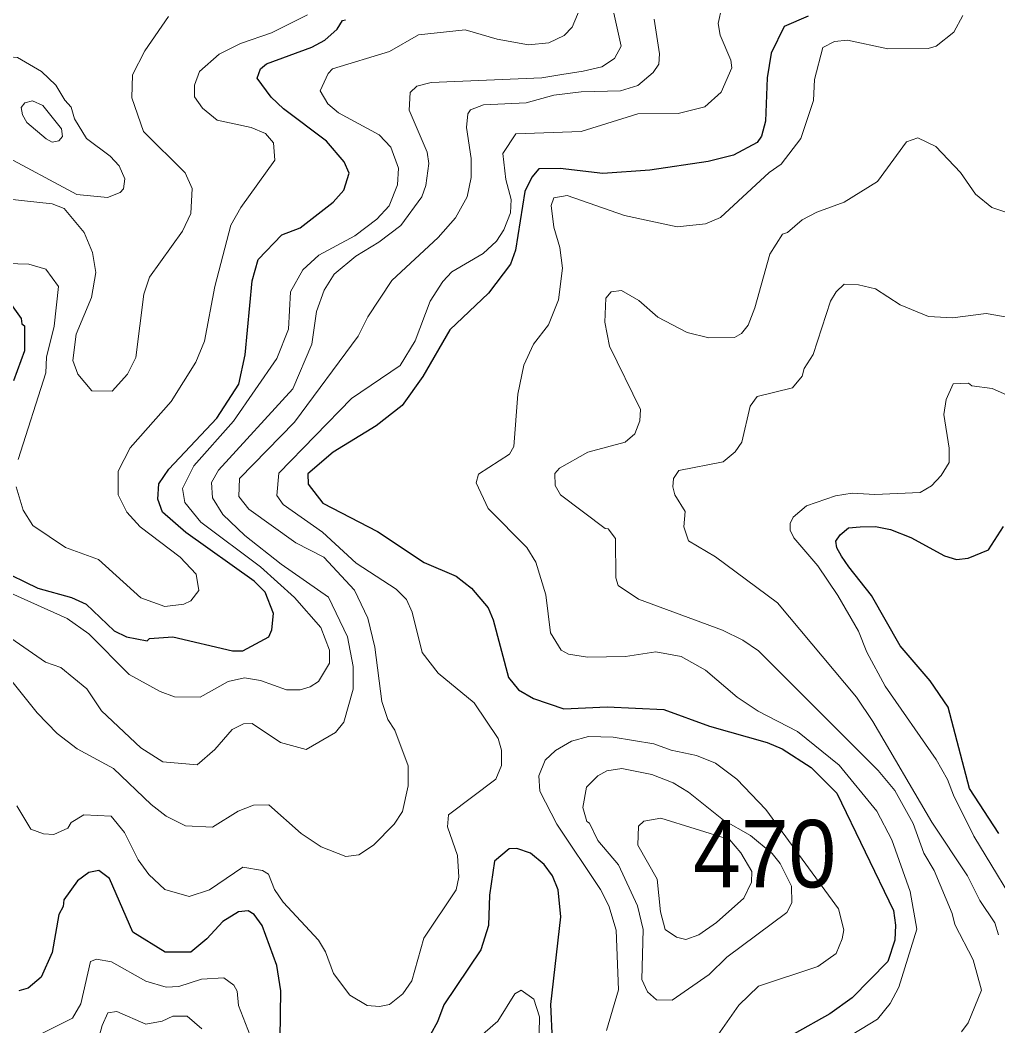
# Model space of a CAD drawing. Extents: x 673.3 to 698.5, y 6984.3 to 7012.3.
# Drawn here: x 690.061 to 691.219, y 6996.578 to 6997.77 of the extents above; entities that cross this region are included whole.
import ezdxf

# ---------------------------------------------------------------- set-up
doc = ezdxf.new("R2010")
doc.units = 0
doc.header["$LTSCALE"] = 0.032
doc.layers.add('1', color=7, linetype='Continuous', lineweight=25)
doc.layers.add('2', color=7, linetype='Continuous', lineweight=13)
doc.layers.add('21', color=7, linetype='Continuous')

msp = doc.modelspace()

# ---------------------------------------------------------------- linework, layer by layer
at = {"layer": '1'}
for points in [[(690.2418, 6997.0396), (690.3124, 6997.0228), (690.3249, 6997.0227), (690.3556, 6997.0394), (690.3593, 6997.0478), (690.361, 6997.0673), (690.3512, 6997.0925), (690.3383, 6997.1056), (690.2572, 6997.1631), (690.2298, 6997.187), (690.2243, 6997.2025), (690.2252, 6997.2209), (690.237, 6997.2381), (690.2942, 6997.2985), (690.3202, 6997.3389), (690.3276, 6997.3735), (690.3357, 6997.4612), (690.3431, 6997.4867), (690.3712, 6997.5159), (690.3927, 6997.5242), (690.4318, 6997.5544), (690.4443, 6997.5687), (690.4507, 6997.5889), (690.4449, 6997.6024), (690.4239, 6997.6266), (690.373, 6997.6649), (690.3585, 6997.6789), (690.3419, 6997.7014), (690.3457, 6997.7124), (690.3529, 6997.7183), (690.4066, 6997.7383), (690.4218, 6997.7464), (690.4364, 6997.7593), (690.4431, 6997.7699), (690.4465, 6997.7705)], [(690.9947, 6997.775), (690.9661, 6997.7627), (690.9509, 6997.7311), (690.9458, 6997.7017), (690.9441, 6997.6504), (690.9392, 6997.6326), (690.9343, 6997.6253), (690.9063, 6997.6102), (690.876, 6997.6025), (690.807, 6997.5926), (690.7513, 6997.5886), (690.7007, 6997.5943), (690.6754, 6997.5941), (690.6671, 6997.5841), (690.659, 6997.5671), (690.6477, 6997.4976), (690.6419, 6997.4811), (690.6157, 6997.4466), (690.5699, 6997.4034), (690.5379, 6997.3478), (690.5134, 6997.3135), (690.4827, 6997.2896), (690.4317, 6997.2584), (690.4019, 6997.2326), (690.4022, 6997.2205), (690.4198, 6997.198), (690.4845, 6997.1644), (690.5396, 6997.1275), (690.5776, 6997.1113), (690.5957, 6997.0972), (690.6153, 6997.074)], [(690.0483, 6997.4361), (690.0624, 6997.4166), (690.063, 6997.4105), (690.0662, 6997.4081), (690.0662, 6997.3784), (690.0533, 6997.3429)], [(691.2204, 6996.8065), (691.1855, 6996.8599), (691.1605, 6996.956), (691.1389, 6996.9873), (691.1035, 6997.0289), (691.0697, 6997.0883), (691.0428, 6997.1224), (691.0339, 6997.1351), (691.0285, 6997.1448), (691.0273, 6997.1528), (691.0325, 6997.1605), (691.0423, 6997.1685), (691.0562, 6997.1698), (691.0744, 6997.1702), (691.092, 6997.1667), (691.1162, 6997.1573), (691.1562, 6997.1355), (691.1703, 6997.131), (691.1842, 6997.1327), (691.208, 6997.1427), (691.226, 6997.1702)], [(690.0347, 6997.1201), (690.082, 6997.0973), (690.1219, 6997.0859), (690.1392, 6997.0781), (690.1723, 6997.0464), (690.1871, 6997.0393), (690.2116, 6997.0348), (690.2143, 6997.0373), (690.2418, 6997.0396)], [(690.6153, 6997.074), (690.6212, 6997.0595), (690.6394, 6996.9911), (690.6516, 6996.9765), (690.6691, 6996.9662), (690.705, 6996.9541), (690.7565, 6996.9565), (690.8236, 6996.9533), (690.8776, 6996.9336), (690.946, 6996.9141), (690.9639, 6996.9068), (690.9981, 6996.8847), (691.0286, 6996.8542), (691.0956, 6996.7152), (691.098, 6996.6979), (691.0972, 6996.6801), (691.0891, 6996.6547), (691.0465, 6996.6118), (691.0201, 6996.5927), (690.9356, 6996.5453)], [(690.6916, 6996.5612), (690.6896, 6996.604), (690.7014, 6996.7078), (690.6982, 6996.7396), (690.6916, 6996.7562), (690.682, 6996.7698), (690.6655, 6996.7831), (690.6493, 6996.7887), (690.6403, 6996.7883), (690.6231, 6996.7736), (690.617, 6996.7334), (690.6159, 6996.6976), (690.6069, 6996.6684), (690.5631, 6996.6034), (690.5555, 6996.5833), (690.5389, 6996.5533)], [(690.3692, 6996.5636), (690.3699, 6996.6201), (690.3652, 6996.65), (690.3479, 6996.6976), (690.3382, 6996.7106), (690.3313, 6996.7147), (690.3196, 6996.7135), (690.3013, 6996.7022), (690.2823, 6996.6816), (690.2633, 6996.6659), (690.2327, 6996.6658), (690.1947, 6996.6897), (690.167, 6996.753), (690.1541, 6996.7626), (690.1425, 6996.7601), (690.1289, 6996.7505), (690.1128, 6996.728), (690.1119, 6996.7201), (690.1069, 6996.7106), (690.0988, 6996.6653), (690.0859, 6996.636), (690.0707, 6996.6231), (690.0594, 6996.6202)]]:
    msp.add_lwpolyline(points, dxfattribs=at)
at = {"layer": '2'}
for points in [[(690.0303, 6997.0999), (690.1169, 6997.061), (690.1424, 6997.043), (690.19, 6996.9949), (690.2268, 6996.9747), (690.2437, 6996.9684), (690.2742, 6996.9678), (690.3075, 6996.9867), (690.3268, 6996.9907), (690.3458, 6996.9877), (690.3767, 6996.9768), (690.3926, 6996.9768), (690.4046, 6996.9802), (690.4144, 6996.9867), (690.4277, 6997.0084), (690.4276, 6997.0235), (690.4174, 6997.0506), (690.3862, 6997.086), (690.3458, 6997.1224), (690.275, 6997.1753), (690.256, 6997.1988), (690.2534, 6997.2154), (690.2668, 6997.2419), (690.3139, 6997.2948), (690.3653, 6997.3692), (690.3788, 6997.4039), (690.3813, 6997.4484), (690.3958, 6997.4743), (690.4147, 6997.4916), (690.4577, 6997.5147), (690.4836, 6997.5344), (690.4981, 6997.55), (690.5082, 6997.5749), (690.5092, 6997.5947), (690.5, 6997.6198), (690.4863, 6997.6342), (690.4383, 6997.6602), (690.4257, 6997.6711), (690.4166, 6997.6866), (690.426, 6997.7071), (690.4312, 6997.7123), (690.4984, 6997.7329), (690.533, 6997.7527), (690.5884, 6997.7588), (690.626, 6997.7478), (690.6632, 6997.7409), (690.6874, 6997.7434), (690.7057, 6997.7519), (690.7148, 6997.7618), (690.736, 6997.8121)], [(690.7628, 6997.7854), (690.773, 6997.7393), (690.7653, 6997.7249), (690.7502, 6997.7148), (690.728, 6997.7097), (690.7028, 6997.7058), (690.679, 6997.7019), (690.548, 6997.6962), (690.5311, 6997.6921), (690.5231, 6997.6844), (690.522, 6997.6636), (690.5432, 6997.6136), (690.545, 6997.6003), (690.5418, 6997.5743), (690.5368, 6997.5609), (690.512, 6997.527), (690.486, 6997.507), (690.4587, 6997.4907), (690.433, 6997.469), (690.421, 6997.4502), (690.4121, 6997.4249), (690.4064, 6997.3862), (690.3842, 6997.3335), (690.296, 6997.237), (690.2877, 6997.2225), (690.2889, 6997.204), (690.301, 6997.1844), (690.3274, 6997.1596), (690.3702, 6997.1257), (690.4264, 6997.0864), (690.449, 6997.0393), (690.4554, 6997.0045), (690.4554, 6996.9774), (690.4446, 6996.9384), (690.4346, 6996.926), (690.3999, 6996.9061), (690.3696, 6996.9144), (690.3359, 6996.9368), (690.3258, 6996.9362), (690.3121, 6996.9296), (690.2915, 6996.9058), (690.2707, 6996.8878), (690.2302, 6996.8914), (690.2041, 6996.9081), (690.1573, 6996.9519), (690.1401, 6996.978), (690.1091, 6997.0031), (690.0911, 6997.0093), (690.0399, 6997.0448)], [(690.8921, 6997.7858), (690.888, 6997.7661), (690.8902, 6997.7524), (690.9031, 6997.7228), (690.904, 6997.7137), (690.8913, 6997.6849), (690.8722, 6997.6675), (690.8405, 6997.6594), (690.7926, 6997.6593), (690.7257, 6997.6382), (690.6481, 6997.6354), (690.633, 6997.6123), (690.6364, 6997.5813), (690.6427, 6997.5576), (690.642, 6997.5417), (690.6342, 6997.5217), (690.6255, 6997.5082), (690.6095, 6997.4935), (690.5725, 6997.4718), (690.5617, 6997.4606), (690.5466, 6997.437), (690.5289, 6997.3901), (690.5113, 6997.361), (690.4536, 6997.322), (690.3676, 6997.2333), (690.3651, 6997.2069), (690.3728, 6997.1964), (690.4194, 6997.1636), (690.4591, 6997.1269), (690.5066, 6997.0958), (690.5189, 6997.0837), (690.5255, 6997.0686), (690.5374, 6997.0208), (690.5563, 6996.9966), (690.599, 6996.9612), (690.6274, 6996.9188), (690.6312, 6996.905), (690.6313, 6996.8869), (690.6246, 6996.8709), (690.5686, 6996.8284), (690.5671, 6996.8143), (690.5793, 6996.7803), (690.5809, 6996.7548), (690.5776, 6996.7395), (690.5391, 6996.6824), (690.525, 6996.6318), (690.5142, 6996.6164)], [(690.0445, 6997.5583), (690.0988, 6997.5526), (690.1132, 6997.5471), (690.137, 6997.5184), (690.1466, 6997.4947), (690.1508, 6997.4712), (690.1455, 6997.4415), (690.1273, 6997.398), (690.1233, 6997.367), (690.1292, 6997.3507), (690.1461, 6997.3308), (690.1699, 6997.3306), (690.1881, 6997.3505), (690.1981, 6997.3704), (690.2076, 6997.4456), (690.2142, 6997.4658), (690.2535, 6997.5203), (690.2631, 6997.5411), (690.2648, 6997.5706), (690.2567, 6997.5893), (690.2072, 6997.6384), (690.1933, 6997.6781), (690.194, 6997.7053), (690.2089, 6997.7338), (690.2368, 6997.7745)], [(690.4015, 6997.7765), (690.3589, 6997.7552), (690.3219, 6997.7424), (690.2967, 6997.7299), (690.2734, 6997.7093), (690.2674, 6997.693), (690.2674, 6997.6793), (690.277, 6997.666), (690.2946, 6997.6517), (690.3349, 6997.643), (690.3518, 6997.6358), (690.361, 6997.6246), (690.3627, 6997.6042), (690.3223, 6997.5483), (690.3107, 6997.5272), (690.2917, 6997.4547), (690.2795, 6997.3899), (690.2691, 6997.3648), (690.2398, 6997.3184), (690.1914, 6997.2634), (690.1771, 6997.2357), (690.1772, 6997.2078), (690.1875, 6997.187), (690.2033, 6997.1698), (690.2506, 6997.1337), (690.2696, 6997.1136), (690.2729, 6997.0943), (690.2631, 6997.082), (690.2548, 6997.0781), (690.2323, 6997.0755), (690.2042, 6997.0857), (690.1539, 6997.1309), (690.1148, 6997.1452), (690.0762, 6997.1714), (690.0646, 6997.1897), (690.0565, 6997.2172)], [(690.5043, 6996.8173), (690.5141, 6996.8323), (690.5206, 6996.863), (690.5206, 6996.8865), (690.5051, 6996.9289), (690.4966, 6996.9414), (690.4897, 6996.9628), (690.4814, 6997.0273), (690.4731, 6997.0615), (690.4572, 6997.0948), (690.4207, 6997.1339), (690.3876, 6997.1508), (690.332, 6997.1908), (690.3202, 6997.2056), (690.3208, 6997.2272), (690.3862, 6997.2937), (690.4615, 6997.3957), (690.473, 6997.4185), (690.5013, 6997.4618), (690.5562, 6997.5126), (690.5768, 6997.5359), (690.5906, 6997.5609), (690.5955, 6997.5836), (690.5955, 6997.6064), (690.5898, 6997.643), (690.5912, 6997.6591), (690.5946, 6997.664), (690.61, 6997.67), (690.6604, 6997.6723), (690.6933, 6997.6813), (690.7258, 6997.6854), (690.7721, 6997.6864), (690.7929, 6997.6929), (690.8111, 6997.708), (690.8176, 6997.7181), (690.8186, 6997.7302), (690.8121, 6997.7715)], [(690.9106, 6996.9678), (690.873, 6996.9999), (690.8441, 6997.0163), (690.8142, 6997.0218), (690.7782, 6997.0161), (690.733, 6997.0153), (690.7105, 6997.019), (690.7021, 6997.0236), (690.6892, 6997.0443), (690.6837, 6997.0891), (690.6719, 6997.1279), (690.6612, 6997.1452), (690.6155, 6997.1914), (690.6013, 6997.222), (690.604, 6997.2321), (690.6406, 6997.2558), (690.6459, 6997.265), (690.6508, 6997.3269), (690.6576, 6997.3612), (690.6692, 6997.3862), (690.6871, 6997.4093), (690.6989, 6997.4388), (690.7037, 6997.4763), (690.7005, 6997.5006), (690.6932, 6997.525), (690.69, 6997.5507), (690.6931, 6997.5596), (690.7092, 6997.5624), (690.7768, 6997.5388), (690.8394, 6997.5251), (690.873, 6997.5288), (690.8906, 6997.5365), (690.9484, 6997.5897), (690.9626, 6997.5997), (690.9858, 6997.6299), (691.001, 6997.6749), (691.0021, 6997.6999), (691.0121, 6997.7379), (691.0258, 6997.7449), (691.0413, 6997.7466), (691.089, 6997.736), (691.1369, 6997.7366), (691.1463, 6997.7393), (691.167, 6997.756), (691.1777, 6997.7755)], [(690.7, 6997.2393), (690.7334, 6997.2584), (690.7778, 6997.2702), (690.7894, 6997.2801), (690.795, 6997.2954), (690.7958, 6997.309), (690.7594, 6997.384), (690.7536, 6997.4124), (690.755, 6997.4406), (690.761, 6997.4483), (690.7733, 6997.4499), (690.794, 6997.438), (690.8165, 6997.4184), (690.8512, 6997.4002), (690.8767, 6997.3937), (690.9071, 6997.3943), (690.9157, 6997.3989), (690.9234, 6997.4088), (690.9315, 6997.4294), (690.9491, 6997.4927), (690.9642, 6997.5164), (690.9701, 6997.5185), (690.9873, 6997.5336), (691.0049, 6997.5428), (691.0372, 6997.5545), (691.0767, 6997.5788), (691.1109, 6997.6258), (691.1244, 6997.6307), (691.1458, 6997.6204), (691.1752, 6997.5896), (691.1927, 6997.5639), (691.2121, 6997.548), (691.2394, 6997.539)], [(690.0588, 6997.2494), (690.0914, 6997.3524), (690.0924, 6997.371), (690.1012, 6997.4077), (690.1066, 6997.4544), (690.0915, 6997.4751), (690.0714, 6997.481), (690.0454, 6997.4818)], [(691.2201, 6996.6864), (691.2155, 6996.7004), (691.198, 6996.7272), (691.1835, 6996.7562), (691.1411, 6996.8197), (691.0713, 6996.9392), (691.0517, 6996.9678), (690.9583, 6997.0799), (690.8846, 6997.1341), (690.8528, 6997.1531), (690.8472, 6997.1697), (690.8488, 6997.1878), (690.8365, 6997.2077), (690.8342, 6997.217), (690.8351, 6997.2271), (690.8415, 6997.2366), (690.8937, 6997.2467), (690.9081, 6997.2586), (690.9161, 6997.2701), (690.926, 6997.3126), (690.9341, 6997.3243), (690.9759, 6997.3343), (690.9876, 6997.3484), (690.9898, 6997.3575), (691.0005, 6997.3741), (691.0212, 6997.4373), (691.0278, 6997.4482), (691.0373, 6997.4574), (691.0542, 6997.4566)], [(691.0542, 6997.4566), (691.0744, 6997.4517), (691.1035, 6997.4329), (691.1373, 6997.4189), (691.1654, 6997.4175), (691.2056, 6997.4224), (691.235, 6997.4176)], [(691.0059, 6997.1235), (690.9774, 6997.1569), (690.9734, 6997.1658), (690.9734, 6997.1738), (690.9767, 6997.1813), (690.9924, 6997.1948), (691.0269, 6997.2065), (691.0467, 6997.2098), (691.0737, 6997.2082), (691.1271, 6997.2105), (691.1405, 6997.2182), (691.1522, 6997.2307), (691.1615, 6997.246), (691.1615, 6997.2631), (691.1551, 6997.3028), (691.1581, 6997.3208), (691.1663, 6997.3394), (691.1846, 6997.3402), (691.1883, 6997.3369), (691.2125, 6997.3337), (691.268, 6997.3093)], [(691.1761, 6996.5715), (691.184, 6996.5821), (691.1997, 6996.6206), (691.19, 6996.6569), (691.1683, 6996.6986), (691.1651, 6996.7117), (691.1437, 6996.7624), (691.1316, 6996.7833), (691.119, 6996.8184), (691.0971, 6996.8572), (691.0773, 6996.8811), (690.9357, 6997.0227), (690.917, 6997.0357), (690.8931, 6997.0473), (690.7936, 6997.0839), (690.7696, 6997.1002), (690.7666, 6997.1095), (690.7664, 6997.1561), (690.7578, 6997.1673), (690.7541, 6997.1678), (690.7011, 6997.2079), (690.695, 6997.2186), (690.6945, 6997.233), (690.7, 6997.2393)], [(691.2537, 6996.6998), (691.191, 6996.8032), (691.1667, 6996.8518), (691.1598, 6996.8705), (691.1463, 6996.8942), (691.0857, 6996.9811), (691.064, 6997.0211), (691.054, 6997.0461), (691.0297, 6997.0883), (691.0059, 6997.1235)], [(690.0094, 6997.0386), (690.0813, 6996.9495), (690.105, 6996.9251), (690.1286, 6996.9067), (690.1718, 6996.8834), (690.2162, 6996.8407), (690.2342, 6996.8269), (690.2571, 6996.8156), (690.289, 6996.8141), (690.3195, 6996.8327), (690.3376, 6996.8399), (690.3555, 6996.8402), (690.3938, 6996.8065), (690.4175, 6996.7906), (690.4467, 6996.7792), (690.4621, 6996.7811), (690.4797, 6996.7926), (690.5043, 6996.8173)], [(691.0363, 6996.562), (691.0765, 6996.5865), (691.0917, 6996.605), (691.1021, 6996.6243), (691.1231, 6996.6929), (691.1153, 6996.7377), (691.0938, 6996.7989), (691.076, 6996.8328), (691.0313, 6996.8872), (690.9818, 6996.9271), (690.9354, 6996.9515), (690.9106, 6996.9678)], [(690.8848, 6996.5635), (690.9123, 6996.6031), (690.9357, 6996.6256), (691.006, 6996.6488), (691.0277, 6996.6644), (691.035, 6996.6815), (691.0368, 6996.6924), (691.0306, 6996.7173), (690.9445, 6996.8349), (690.9099, 6996.871), (690.8846, 6996.8897), (690.8624, 6996.8988), (690.8323, 6996.9051), (690.8119, 6996.9126), (690.7636, 6996.9207), (690.7343, 6996.9215), (690.7142, 6996.9157), (690.6952, 6996.9046), (690.6828, 6996.8932), (690.6754, 6996.8748), (690.6767, 6996.8566), (690.6967, 6996.8175), (690.7485, 6996.7402), (690.7583, 6996.7207), (690.7672, 6996.6917), (690.7698, 6996.621), (690.7555, 6996.5732)], [(690.5142, 6996.6164), (690.4986, 6996.604), (690.4868, 6996.6016), (690.4722, 6996.6028), (690.4514, 6996.6147), (690.4323, 6996.6404), (690.4229, 6996.6663), (690.4145, 6996.68), (690.3726, 6996.725), (690.3625, 6996.7402), (690.3553, 6996.7583), (690.3481, 6996.7627), (690.3249, 6996.7666), (690.2855, 6996.7397), (690.2611, 6996.7319), (690.2326, 6996.7399), (690.2136, 6996.7577), (690.2007, 6996.7752), (690.1846, 6996.8077), (690.169, 6996.8271), (690.1366, 6996.8286), (690.1213, 6996.8194), (690.1176, 6996.8128), (690.1009, 6996.8051), (690.0888, 6996.8059), (690.0738, 6996.8116), (690.0573, 6996.8393)], [(690.0717, 6996.5621), (690.1232, 6996.5878), (690.1331, 6996.6046), (690.1444, 6996.6547), (690.1516, 6996.6576), (690.1694, 6996.6544), (690.2098, 6996.6315), (690.2339, 6996.6243), (690.2491, 6996.6252), (690.276, 6996.634), (690.3023, 6996.6356), (690.3143, 6996.6267), (690.3181, 6996.6195), (690.3199, 6996.6025), (690.3444, 6996.5386)], [(690.5819, 6996.5448), (690.627, 6996.5841), (690.647, 6996.6163), (690.6544, 6996.6208), (690.6696, 6996.6101), (690.6764, 6996.5892), (690.6754, 6996.5505)], [(690.1473, 6996.539), (690.1583, 6996.579), (690.1648, 6996.594), (690.1755, 6996.5957), (690.2098, 6996.5804), (690.2291, 6996.5839), (690.2421, 6996.59), (690.2588, 6996.59), (690.2762, 6996.5751)]]:
    msp.add_lwpolyline(points, dxfattribs=at)
for points in [[(690.128, 6997.5634), (690.0364, 6997.6126), (690.0226, 6997.6287), (690.0182, 6997.6389), (690.0182, 6997.6917), (690.0214, 6997.709), (690.0289, 6997.7196), (690.0481, 6997.7268), (690.058, 6997.7261), (690.0863, 6997.7092), (690.1032, 6997.6932), (690.1139, 6997.6753), (690.1216, 6997.6672), (690.1256, 6997.6531), (690.1398, 6997.6298), (690.1678, 6997.609), (690.1784, 6997.5975), (690.1849, 6997.582), (690.1836, 6997.5704), (690.1795, 6997.5659), (690.1645, 6997.5599)], [(690.0638, 6997.6579), (690.0623, 6997.6666), (690.0667, 6997.6721), (690.0758, 6997.6747), (690.0879, 6997.6692), (690.11, 6997.6413), (690.1112, 6997.6323), (690.107, 6997.6272), (690.099, 6997.6256), (690.092, 6997.6294), (690.0689, 6997.649)], [(690.8526, 6996.8555), (690.8345, 6996.8664), (690.8095, 6996.8763), (690.7737, 6996.8833), (690.756, 6996.8808), (690.7452, 6996.8749), (690.7318, 6996.8615), (690.7275, 6996.8371), (690.7324, 6996.8208), (690.7355, 6996.8188), (690.7452, 6996.7982), (690.7698, 6996.7692), (690.7925, 6996.7207), (690.7991, 6996.6927), (690.7975, 6996.6333), (690.8044, 6996.6189), (690.8148, 6996.6095), (690.8333, 6996.6089), (690.8773, 6996.6392), (690.8983, 6996.66), (690.9694, 6996.7129), (690.9752, 6996.7242), (690.975, 6996.744), (690.9614, 6996.7707), (690.9519, 6996.7826), (690.9262, 6996.804), (690.8942, 6996.8223)], [(690.8199, 6996.8247), (690.7998, 6996.8211), (690.7934, 6996.815), (690.7926, 6996.7925), (690.8156, 6996.7524), (690.8195, 6996.7137), (690.8253, 6996.6927), (690.8385, 6996.6837), (690.8498, 6996.6807), (690.865, 6996.6864), (690.8859, 6996.701), (690.9184, 6996.7297), (690.9275, 6996.7488), (690.9278, 6996.7614), (690.9149, 6996.7837), (690.9014, 6996.7994)]]:
    msp.add_lwpolyline(points, close=True, dxfattribs=at)

# ---------------------------------------------------------------- texts
at = {"layer": '21', "width": 0.95}
msp.add_text('470', height=0.08, dxfattribs=at).set_placement((690.8582, 6996.7425))

doc.saveas('drawing.dxf')
